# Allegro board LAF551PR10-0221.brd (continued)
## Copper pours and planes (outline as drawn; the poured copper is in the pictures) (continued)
N19529526 on BOTTOM (solid shape): 41.06,10.36 41.06,8.66 40.65,8.25 40.01,8.88 40.01,9.52 39.51,10.02 39.51,10.79 39.62,10.9 40.52,10.9
N19529527 on TOP (solid shape): 34.34,8.45 34.34,7.64 34.42,7.56 34.42,6.79 34.55,6.66 34.6,6.6 34.66,6.55 34.8,6.41 35.06,6.41 35.12,6.35 35.12,5.46 35.05,5.4 34.33,5.4 34.25,5.48 34.25,6.51 34.14,6.62 34.14,8.45 34.19,8.5 34.29,8.5
N19529528 on TOP (solid shape): 33.95,8.45 33.95,7.59 33.99,7.55 33.99,6.58 34.1,6.46 34.1,5.58 34.04,5.52 33.47,5.52 33.47,6.69 33.72,6.94 33.72,7.6 33.73,7.61 33.73,8.44 33.8,8.5 33.9,8.5
N19529529 on TOP (solid shape): 30.95,9.48 30.95,9.36 30.88,9.29 30.06,9.29 29.56,8.79 29.56,8.46 29.41,8.31 28.77,8.31 28.65,8.44 28.65,9.26 28.72,9.33 29.21,9.33 29.42,9.55 30.88,9.55
N19616930 on TOP (solid shape): 226.85,118.47 226.85,116.72 226.84,116.71 226.81,116.58 226.84,116.45 226.85,116.44 226.85,115.23 226.84,115.22 226.84,113.36 226.88,113.31 226.85,113.28 226.78,112.91 227.11,112.73 227.25,112.59 227.25,112.11 227.11,111.97 226.15,111.97 225.97,112.15 225.97,112.94 225.97,112.95 225.99,113.05 225.97,113.15 225.97,113.16 225.97,113.64 225.97,113.65 225.99,113.75 225.97,113.85 225.97,113.86 225.97,115.61 226.06,115.7 226.06,116.67 225.76,116.96 224.57,116.96 223.85,117.68 223.85,118.48 223.94,118.57 226.75,118.57
N20124859 on BOTTOM (solid shape): 176.28,170.92 176.28,167.62 176.26,167.59 175.22,167.59 175.01,167.8 175.01,169.6 175.32,169.9 175.32,170.95 175.37,171 176.21,171
N20124859 on IN6 (solid shape): outline of 105 points within 174.86,164.46 182.29,171.55
N20496102 on TOP (solid shape): 31.25,4.5 31.25,3.67 31.31,3.61 31.31,3.1 31.19,2.98 30.68,2.98 30.62,3.04 30.62,4.5 30.68,4.56 31.19,4.56
N20496104 on TOP (solid shape): 35.66,5.01 35.66,4.16 36.08,3.74 36.08,3.17 36.01,3.1 35.51,3.1 35.44,3.17 35.44,3.41 35.47,3.55 35.44,3.69 35.44,3.71 35.41,3.74 35.37,3.8 35.31,3.85 34.97,4.18 34.97,5.03 35.02,5.08 35.58,5.08
N20496105 on BOTTOM (solid shape): 40.6,7.01 40.6,6.86 40.21,6.47 39.75,6.47 39.43,6.15 38.9,6.15 38.86,6.19 38.86,6.74 38.92,6.8 39.57,6.8 40.18,7.41 40.2,7.41
N21000719 on BOTTOM (solid shape): outline of 90 points within 170.98,159.89 172.73,162.57
N21643800 on TOP (solid shape): 309.52,53.75 309.52,52.53 310.05,52 310.05,51.31 309.84,51.09 308.17,51.09 308.09,51.17 308.09,51.78 308.61,52.3 308.61,53.45 308.48,53.58 308,53.58 307.88,53.69 307.88,54.25 307.97,54.33 308.94,54.33
N21643800 on BOTTOM (solid shape): 289.46,46.98 289.46,45.84 289.16,45.55 288.81,45.55 288.3,46.06 288.3,46.92 288.54,47.17 289.27,47.17
N21643800 on BOTTOM (solid shape): 289.39,41.28 289.39,40.9 289.15,40.66 289.15,40.22 289.06,40.14 288.09,40.14 287.91,40.31 287.91,41.35 287.99,41.43 289.23,41.43
N21643800 on IN1 (solid shape): 290.3,46.5 290.3,45.61 290.14,45.46 288.56,45.46 288.31,45.7 288.31,46.45 288.42,46.56 290.24,46.56
N21643800 on IN1 (solid shape): 309.35,52.92 309.35,51 309.28,50.92 308.41,50.92 308.34,50.99 308.34,52.94 308.47,53.07 309.2,53.07
N21643800 on IN2 (solid shape): 289.44,46.19 289.44,44.51 289.32,44.38 288.51,44.38 288.43,44.47 288.43,45.13 288.31,45.25 288.31,46.4 288.48,46.57 289.06,46.57
N21643800 on IN2 (solid shape): 289.44,42 289.44,40.92 289.19,40.67 289.19,40.3 288.76,39.87 288.16,39.87 287.89,40.14 287.89,40.67 288.43,41.21 288.43,41.98 288.52,42.08 289.36,42.08
N21646778 on TOP (solid shape): 297.82,55.97 297.82,55.38 298.12,55.08 299,55.08 299.1,54.98 299.1,54.36 299.01,54.28 298.36,54.28 297.91,53.83 297.24,53.83 296.74,54.33 296.74,55.98 296.81,56.05 297.75,56.05
N21646778 on BOTTOM (solid shape): 287.56,46.17 287.56,44.65 287.36,44.45 286.87,44.45 286.7,44.62 286.7,46.13 286.86,46.3 287.44,46.3
N21646778 on BOTTOM (solid shape): 287.96,51.71 287.96,50.62 287.56,50.21 286.81,50.21 286.58,50.45 286.58,51.21 286.6,51.22 286.78,51.43 286.76,51.7 286.76,51.8 286.85,51.85 287.82,51.85
N21646778 on IN1 (solid shape): 289.44,51.74 289.44,50.77 289.4,50.73 286.89,50.73 286.83,50.79 286.83,51.68 286.94,51.79 289.39,51.79
N21646778 on IN1 (solid shape): 297.81,55.93 297.81,54.57 297.01,53.77 296.83,53.77 296.3,54.29 296.3,54.5 296.78,54.97 296.78,55.95 296.92,56.09 297.65,56.09
N21646778 on IN2 (solid shape): 287.28,47.21 287.28,46.47 287.56,46.2 287.56,45.45 287.38,45.27 287.06,45.27 286.27,46.06 286.27,47.25 286.31,47.29 287.2,47.29
N21646778 on IN2 (solid shape): 287.94,51.68 287.94,51.14 287.37,50.58 287.37,50.58 287.29,50.5 287.29,50.22 287.21,50.14 286.34,50.14 286.27,50.22 286.27,51.1 286.36,51.19 286.39,51.19 286.7,51.29 286.8,51.6 286.79,51.62 287.01,51.85 287.77,51.85
N21748624 on TOP (solid shape): 80.84,30.22 82.05,30.22 82.24,30.03 82.24,28.95 82.11,28.82 79.57,28.82 79.45,28.95 79.45,30.47 79.51,30.53 80.53,30.53
N24654525 on TOP (solid shape): outline of 114 points within 225.75,38.54 229,44.38
N26232649 on TOP (solid shape): 208.23,31.17 208.23,30.53 208.03,30.34 206.89,30.34 206.76,30.47 206.76,31.23 206.96,31.42 207.97,31.42
N26956300 on BOTTOM (solid shape): 32.14,17.71 32.14,16.12 31.76,15.74 29.09,15.74 29.03,15.8 29.03,16.37 29.22,16.56 31.12,16.56 31.44,16.88 31.44,17.64 31.63,17.83 32.01,17.83
N28601066 on BOTTOM (solid shape): 153.93,151.45 153.93,150.6 153.66,150.33 153.12,150.33 153.07,150.28 153,150.23 152.94,150.16 152.85,150.06 152.85,149.51 152.81,149.47 152.58,149.47 152.51,149.54 152.51,150.26 152.77,150.52 152.8,150.52 152.8,150.55 152.87,150.62 152.87,151.43 152.99,151.55 153.83,151.55
N28601068 on BOTTOM (solid shape): 152.74,151.38 152.74,150.68 152.37,150.31 152.16,150.31 152.14,150.31 152,150.23 151.92,150.08 151.92,150.07 151.88,150.03 151.88,149.57 151.77,149.47 151.6,149.47 151.52,149.55 151.52,150.1 151.72,150.31 151.72,151.43 151.77,151.48 152.64,151.48
N28601070 on BOTTOM (solid shape): 154.05,152.68 154.05,152.15 153.92,152.02 151.86,152.02 151.74,152.15 151.74,152.73 151.79,152.78 153.95,152.78
N28601086 on TOP (solid shape): 153.48,144.1 153.48,141.43 153.22,141.18 152.31,141.18 152.15,141.33 152.15,144.07 152.28,144.2 153.37,144.2
N28601170 on BOTTOM (solid shape): 161.79,149.68 161.79,149.15 161.67,149.02 159.61,149.02 159.48,149.15 159.48,149.73 159.53,149.78 161.69,149.78
N28601172 on BOTTOM (solid shape): 161.74,148.28 161.74,147.77 161.14,147.17 161.07,147.17 161.07,147.17 160.85,147.14 160.72,146.96 160.71,146.95 160.65,146.89 160.65,146.41 160.58,146.34 160.4,146.34 160.32,146.41 160.32,147.27 160.58,147.53 160.6,147.53 160.6,147.55 160.68,147.62 160.68,148.26 160.8,148.38 161.64,148.38
N28601174 on BOTTOM (solid shape): 160.52,148.26 160.52,147.77 159.93,147.18 159.91,147.17 159.79,147.1 159.72,146.98 159.72,146.97 159.66,146.91 159.66,146.45 159.56,146.35 159.38,146.35 159.3,146.43 159.3,146.99 159.51,147.19 159.51,147.26 159.51,147.27 159.53,147.39 159.51,147.52 159.51,147.53 159.51,148.31 159.56,148.36 160.42,148.36
N28601188 on TOP (solid shape): 161.2,140.29 161.2,137.6 160.99,137.39 160.21,137.39 160.03,137.57 160.03,140.29 160.16,140.41 161.07,140.41
N28602204 on BOTTOM (solid shape): 168.13,148.21 168.13,147.73 167.53,147.13 167.52,147.13 167.4,147.06 167.33,146.94 167.33,146.92 167.27,146.87 167.27,146.41 167.17,146.31 166.99,146.31 166.91,146.38 166.91,146.94 167.12,147.15 167.12,148.26 167.17,148.31 168.03,148.31
N28602206 on BOTTOM (solid shape): 169.4,149.63 169.4,149.36 169.38,149.33 169.38,149.08 169.27,148.97 167.22,148.97 167.09,149.1 167.09,149.69 167.14,149.74 169.3,149.74
N28602208 on BOTTOM (solid shape): 169.35,148.24 169.35,147.73 169.03,147.41 168.85,147.41 168.58,147.14 168.57,147.14 168.41,147.07 168.33,146.92 168.32,146.9 168.26,146.84 168.26,146.43 168.16,146.33 168.08,146.33 167.93,146.49 167.93,147.22 168.28,147.58 168.28,148.21 168.41,148.34 169.25,148.34
N28602391 on TOP (solid shape): 168.82,140.21 168.82,137.47 168.64,137.29 167.7,137.29 167.5,137.49 167.5,140.29 167.62,140.41 168.61,140.41
N28602475 on BOTTOM (solid shape): 177.82,148.34 177.82,147.16 177.78,147.12 177.35,147.12 177.05,146.82 177.05,146.04 176.97,145.97 176.76,145.97 176.69,146.03 176.69,147.07 176.88,147.26 176.88,148.32 176.94,148.39 177.78,148.39
N28602479 on BOTTOM (solid shape): 176.73,148.32 176.73,147.31 176.36,146.94 176.23,146.94 176.06,146.76 176.06,146.08 175.95,145.96 175.77,145.96 175.7,146.03 175.7,147.11 175.8,147.28 175.79,147.48 175.79,147.6 175.61,147.79 175.61,148.31 175.65,148.35 176.69,148.35
N28602593 on TOP (solid shape): 177.73,140.31 177.73,137.49 177.58,137.34 176.79,137.34 176.46,137.67 176.46,140.21 176.62,140.36 177.68,140.36
N28602604 on BOTTOM (solid shape): 177.86,149.71 177.86,149.13 177.81,149.08 175.68,149.08 175.65,149.1 175.65,149.71 175.7,149.76 177.81,149.76
N28603944 on BOTTOM (solid shape): 144.16,151.88 144.16,150.98 144.24,150.89 144.24,150.78 144.29,150.78 144.29,149.58 144.19,149.48 144.01,149.48 143.94,149.55 143.94,150.11 143.88,150.17 143.88,150.42 143.71,150.59 143.74,150.62 143.72,151.08 143.26,151.14 143.16,151.14 143.11,151.23 143.11,151.9 143.17,151.96 144.07,151.96
N28603948 on BOTTOM (solid shape): 145.42,151.73 145.42,150.21 145.38,150.16 145.35,150.09 145.35,150.07 145.28,150.01 145.28,149.6 145.18,149.5 145.11,149.5 144.95,149.65 144.95,150.02 144.9,150.07 144.9,150.08 144.85,150.2 144.75,150.28 144.75,150.61 144.36,151.01 144.36,151.82 144.41,151.87 145.27,151.87
N28604013 on BOTTOM (solid shape): 183.78,148.26 183.78,147.07 183.65,146.94 183.57,146.94 183.37,146.74 183.37,146.07 183.28,145.98 183.08,145.98 182.99,146.07 182.99,146.87 183.19,147.22 182.95,147.53 182.94,147.54 182.83,147.65 182.83,148.26 182.95,148.39 183.65,148.39
N28604017 on BOTTOM (solid shape): 184.98,148.26 184.98,147.49 184.36,146.87 184.36,146.26 184.24,146.13 184.11,146.13 183.96,146.28 183.96,146.99 183.99,147.03 183.99,148.23 184.1,148.33 184.92,148.33
N28604619 on BOTTOM (solid shape): 145.44,153.28 145.44,152.58 145.43,152.58 145.43,152.37 145.32,152.26 143.28,152.26 143.13,152.41 143.13,153.17 143.13,153.17 143.13,153.34 143.17,153.38 145.33,153.38
N28604630 on TOP (solid shape): 145.91,144.05 145.91,141.25 145.68,141.02 144.89,141.02 144.61,141.3 144.61,143.97 144.76,144.12 145.83,144.12
N28604700 on BOTTOM (solid shape): 185.1,149.62 185.1,149.11 185.02,149.04 182.94,149.04 182.86,149.11 182.86,149.65 182.94,149.72 185,149.72
N28604706 on TOP (solid shape): 184.9,138.53 184.9,135.72 184.82,135.64 183.78,135.64 183.6,135.82 183.6,138.48 183.83,138.71 184.72,138.71
N30964087 on BOTTOM (solid shape): 291.23,89.42 291.23,87.91 290.99,87.67 290.76,87.67 290.6,87.84 290.6,89.49 290.61,89.5 291.16,89.5
N31204217 on TOP (solid shape): 309.4,62.76 309.4,62.36 309.3,62.26 307.08,62.26 307.01,62.33 307.01,62.8 307.04,62.83 309.32,62.83
N31227804 on BOTTOM (solid shape): 289.35,80.33 289.35,79.82 289.21,79.68 287.82,79.68 287.65,79.85 287.65,80.47 287.69,80.51 289.18,80.51
N31483118 on BOTTOM (solid shape): 239.05,36.33 239.05,35.84 238.58,35.37 238.58,35.3 238.57,35.29 238.53,35.11 238.57,34.93 238.58,34.91 238.58,34.88 238.68,34.78 238.72,34.78 238.73,34.77 238.91,34.72 239.09,34.77 239.1,34.78 239.23,34.78 239.35,34.65 239.35,34.22 239.24,34.1 238.38,34.1 238.18,34.29 238.18,34.61 238.12,34.68 238.12,34.69 237.99,34.83 237.99,35.78 238.17,35.96 238.18,35.97 238.34,36.09 238.41,36.28 238.41,36.3 238.53,36.41 238.96,36.41
N31787119 on TOP (solid shape): 256.68,156.36 256.68,155.79 256.17,155.28 254.83,155.28 254.77,155.34 254.77,155.91 254.83,155.98 255.28,155.98 255.72,156.42 256.61,156.42
N32274706 on TOP (solid shape): 284.1,51.76 284.88,51.76 284.95,51.69 284.95,51.41 285,51.36 285,50.35 284.81,50.16 283.66,50.16 280.42,53.39 278.71,53.39 278.52,53.58 278.52,54.41 278.71,54.6 281.25,54.6
N32274706 on TOP (solid shape): 297.62,53.51 297.93,53.51 298.06,53.37 298.06,51.72 298.36,51.43 299.47,51.43 299.54,51.35 299.54,49.34 299.28,49.08 298.74,49.08 298.47,49.34 298.47,50.52 297.2,51.79 297.2,53.31 297.4,53.51 297.62,53.51
N32274706 on BOTTOM (solid shape): outline of 146 points within 277.38,40.87 285.06,56.7
N32295361 on TOP (solid shape): 290.53,52.7 290.53,51.87 290.28,51.62 288.86,51.62 288.68,51.79 288.68,52.98 288.73,53.03 290.2,53.03
N32295361 on TOP (solid shape): 308.81,50.73 308.81,50.22 307.83,49.24 305.28,49.24 305.13,49.39 305.13,49.77 305.16,49.81 305.21,49.81 305.21,49.85 305.25,49.9 306.64,49.9 306.88,50.14 306.88,50.72 306.95,50.79 308.75,50.79
N32295361 on BOTTOM (solid shape): outline of 97 points within 288.11,40.89 293.99,56.95
N32295361 on IN6 (solid shape): 295.28,45.65 295.28,44.89 295.16,44.76 293.06,44.76 292.87,44.95 292.87,45.58 293,45.71 295.22,45.71
N32295361 on IN6 (solid shape): 305.25,49.91 306.1,49.91 306.21,49.81 306.21,49.17 306.08,49.04 303.86,49.04 303.79,49.11 303.79,49.87 303.92,50 305.16,50
N32856423 on TOP (solid shape): 228.1,154.69 228.1,154.1 228.1,154.09 228.2,154 228.2,153.79 228.06,153.66 227.88,153.66 227.72,153.81 227.73,153.93 227.72,154.01 227.72,154.16 227.61,154.28 227.46,154.28 227.39,154.28 227.31,154.28 227.28,154.31 227.28,154.79 227.3,154.81 227.98,154.81
N32856423 on BOTTOM (solid shape): 228.19,154.02 228.19,153.75 227.88,153.44 227.88,152.68 227.78,152.58 227.62,152.58 227.55,152.66 227.55,153.49 227.74,153.68 227.74,153.85 227.73,153.88 227.74,153.96 227.76,154 227.77,154.03 227.77,154.04 227.88,154.16 228.06,154.16
N32856454 on TOP (solid shape): 229.12,154.87 229.12,154.23 229.12,154.23 229.12,153.84 228.9,153.63 228.49,153.63 228.32,153.79 228.32,154.11 228.23,154.21 228.23,154.75 228.23,154.87 228.24,154.88 229.12,154.88
N32856474 on TOP (solid shape): 229.18,156.2 229.18,155.63 228.7,155.15 227.31,155.15 227.28,155.18 227.28,155.76 227.34,155.82 227.78,155.82 228.29,156.33 229.05,156.33
N32868428 on BOTTOM (solid shape): 214.31,154.96 214.31,154.14 214.46,153.99 214.46,153.69 214.23,153.46 214.23,152.68 214.13,152.58 214,152.58 213.9,152.68 213.9,153.69 214,153.8 214,154.05 213.76,154.3 213.66,154.3 213.51,154.45 213.51,155 213.53,155.02 214.25,155.02
N32868434 on BOTTOM (solid shape): 215.25,154.84 215.34,154.83 215.34,154.2 215.34,154.2 215.34,153.59 215.23,153.48 215.23,152.69 215.13,152.59 214.99,152.59 214.89,152.69 214.89,153.47 214.59,153.77 214.59,154.05 214.44,154.2 214.44,154.84 214.46,154.86 215.19,154.86
N32868438 on BOTTOM (solid shape): 215.4,156.2 215.4,155.63 215.31,155.54 215.24,155.53 215.17,155.5 214.45,155.5 214.26,155.31 213.56,155.31 213.5,155.38 213.5,155.95 213.88,156.33 215.27,156.33
N32872467 on TOP (solid shape): 242.83,154.97 242.83,154.06 242.44,153.66 241.95,153.66 241.78,153.83 241.79,153.91 241.78,153.96 241.78,155.02 241.81,155.05 242.76,155.05
N32872467 on BOTTOM (solid shape): 242.61,153.94 242.61,152.76 242.51,152.67 242.35,152.67 242.27,152.75 242.27,153.47 242.06,153.68 241.93,153.69 241.79,153.83 241.79,154.05 241.91,154.17 242.37,154.17
N32872469 on TOP (solid shape): 242.83,156.36 242.83,155.79 242.32,155.28 240.99,155.28 240.93,155.34 240.93,155.91 240.99,155.98 241.44,155.98 241.94,156.49 242.71,156.49
N32872885 on TOP (solid shape): 256.61,154.99 256.61,154.36 256.61,154.36 256.61,154.02 256.34,153.75 255.72,153.75 255.58,153.89 255.58,154.21 255.72,154.35 255.72,154.98 255.74,155 256.61,155
N32872885 on BOTTOM (solid shape): 256.37,154.02 256.37,152.82 256.27,152.72 256.14,152.72 256.06,152.8 256.06,153.59 255.91,153.74 255.76,153.74 255.71,153.75 255.58,153.88 255.58,154.11 255.69,154.22 256.17,154.22

Small or netless copper shapes (teardrops, artwork), in the pictures only: 221 on TOP, 301 on BOTTOM, 1 on IN1, 1 on IN4, 2 on IN6

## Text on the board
Ref Des/Silkscreen Bottom: SPEAKER | HDD/SSD | C17 | FOR | only support for DDR4&JDIMM1/JDIMM2 | TRON LIGHT L | TRON LIGHT R | DC IN | BATTERY | JDIMM1 | JDIMM2 | PK | MK | KB BL | TP | KB | RTC | BL | DDR4 DIMM ONLY | WLAN | PCIE SSD ONLY
User.Comments: LA-F551P | 2018-02-13 | 2019-02-13 | Monika | DDR51
Ref Des/Silkscreen Top: CPU FAN | GPU FAN | TOBII | EDP | POWER | LOGO | USB BOARD
GND4: GND4
IN5: IN5
GND5: GND5
IN6: IN6
GND6: GND6
BODY_CENTER: LAYER | NAME | L3 | L1 | L2 | L5 | L4 | L6 | L7 | L8 | L9 | L10 | L11 | L14 | L12 | L13 | LA-D751P | GND5 | GND2 | GND6 | GND3 | GND4 | TOP | GND1 | IN2 | IN4 | IN3 | IN1 | IN5 | IN6 | BOT | LS-XXXXP
User.44: Width/space | 4.6mil | 4.2 / 3.5 | 3.5 /3.5 | 3 / 3.4 | 5 / 3.6 | 80 ohm
User.45: stack-up setting ok | FIGURE | SIZE | 8.0 | 20.0 | 22.0 | 30.0 | 35.0 | 36.0 | 39.0 | 90.0 | 118.0 | 142.0 | 150.0 | 26.0 | 43.0 | 47.0 | 63.0 | 49.0x28.0 | 55.0x24.0 | 63.0x35.0 | 67.0x24.0 | 69.0x28.0 | 75.0x24.0 | 75.0x28.0 | 79.0x35.0 | 94.0x24.0 | 94.0x28.0 | 161.0x142.0 | 165.0x142.0 | 33.0x26.0 | DRILL CHART: TOP to BOTTOM | ALL UNITS ARE IN MILS | TOLERANCE | +3.0/-3.0 | +2.0/-2.0 | PLATED | NON-PLATED | QTY | 12835 | 10 | 19 | 1 | 8 | 9 | 5 | 14 | 2 | 6 | 4
